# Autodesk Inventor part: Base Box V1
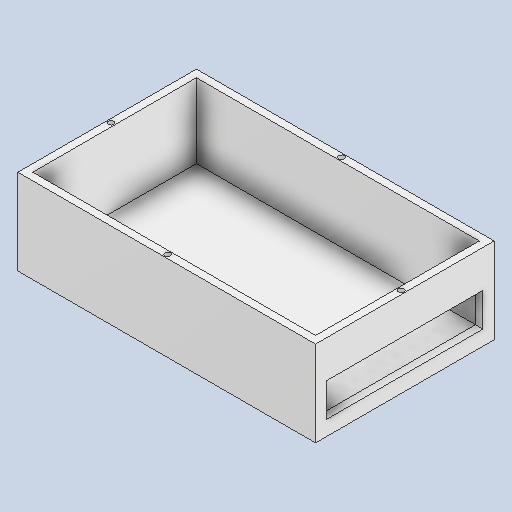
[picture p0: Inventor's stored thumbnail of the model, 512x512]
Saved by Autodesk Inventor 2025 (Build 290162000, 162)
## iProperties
Created: 2024-10
Part Number: Base Box V1
Material: ABS Plastic
Document SubType Name: Modeling
Designer: Braidyn
Density: 1.06 g/cm^3
Appearance: Smooth - White
Author: Braidyn
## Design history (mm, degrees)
sketch "Sketch1"
  geometry: L1 (-35.56, 30.48)-(35.56, 30.48); L2 (35.56, 30.48)-(35.56, -30.48); L3 (35.56, -30.48)-(-35.56, -30.48); L4 (-35.56, -30.48)-(-35.56, 30.48); L5 (-35.56, 30.48)-(35.56, -30.48); L6 (35.56, 30.48)-(-35.56, -30.48); L7 (-35.56, 30.48)-(-66.04, 30.48); L8 (-66.04, 30.48)-(-66.04, -30.48); L9 (-66.04, -30.48)-(-35.56, -30.48); L10 (-35.56, -30.48)-(-35.56, 30.48); 2 further points
  constraints: 20 end point, 4 parallel, 2 horizontal, 2 midpoint, 2 perpendicular
  dimensions: "d0" = 71.12 distance of L2.end L3.end; "d1" = 60.96 distance of L1.end L2.end; "d2" = 30.48 distance of L9.end L8.end
extrude "Extrusion1" new body sketch "Sketch1" distance "d3" = 3.81; taper "d4" = 0 deg
sketch "Sketch2"
  geometry: L1 (0, 0)-(-33.02, 0); L2 (0, 0)-(63.5, 0); L3 (66.04, -30.48)-(66.04, 30.48) reference; L4 (0, 0)-(0, 27.94); L5 (66.04, 30.48)-(-35.56, 30.48) reference; L6 (0, 27.94)-(0, -27.94); L7 (-33.02, -27.94)-(-33.02, 27.94); L8 (-33.02, 27.94)-(63.5, 27.94); L9 (63.5, 27.94)-(63.5, -27.94); L10 (63.5, -27.94)-(-33.02, -27.94); L11 (-35.56, -30.48)-(66.04, -30.48) reference; L12 (-35.56, -30.48)-(-35.56, 30.48); L13 (-35.56, 30.48)-(66.04, 30.48); L14 (66.04, 30.48)-(66.04, -30.48); L15 (66.04, -30.48)-(-35.56, -30.48)
  constraints: 24 end point, 4 perpendicular, 3 parallel, 2 collinear, 1 horizontal, 1 point on line, 1 vertical
  dimensions: "d5" = 33.02 distance of L1.start L1.end; "d6" = 63.5 distance of L1.start L2.end; "d7" = 27.94 distance of L1.start L4.end; "d8" = 55.88 distance of L4.end L6.end
extrude "Extrusion2" join sketch "Sketch2" distance "d9" = 25.4; taper "d10" = 0 deg
sketch "Sketch3"
  geometry: L1 (-33.02, 27.94)-(-33.02, -27.94) reference; L2 (63.5, 27.94)-(-33.02, 27.94) reference; L3 (-33.02, 27.94)-(63.5, 27.94); L4 (15.24, 27.94)-(15.24, 30.48); L5 (66.04, 30.48)-(-35.56, 30.48) reference; L6 (-33.02, -27.94)-(63.5, -27.94) reference; L7 (14.287, -27.94)-(14.287, -30.476); L8 (-35.56, 0)-(-33.02, 0); L9 (63.5, -27.94)-(63.5, 27.94) reference; L10 (63.5, 0)-(66.04, 0); L11 (66.04, -30.48)-(66.04, 30.48) reference; C1 r 0.952 at (15.24, 29.21); C2 r 0.952 at (14.287, -29.208); C3 r 0.953 at (-34.29, 0); C4 r 0.953 at (64.77, 0); 1 further point
  constraints: 10 end point, 9 midpoint, 4 centre point, 1 collinear, 1 perpendicular, 1 point on line
  dimensions: "d11" = 1.905 diameter of C1; "d12" = 1.905 diameter of C2; "d13" = 1.905 diameter of C3; "d14" = 1.905 diameter of C4
extrude "Extrusion3" cut sketch "Sketch3" distance "d15" = 3.81; taper "d16" = 0 deg
sketch "Sketch4"
  geometry: L1 (0, 0)-(0, 3.81); L2 (0, 0)-(0, 29.21) reference; L3 (0, 3.81)-(60.944, 3.81); L4 (0, 3.81)-(0, 5.08); L5 (0, 5.08)-(3.81, 5.08); L6 (60.944, 3.81)-(60.96, 5.08); L7 (60.96, 0)-(60.96, 29.21) reference; L8 (60.96, 5.08)-(57.15, 5.08); L9 (3.81, 5.08)-(57.15, 5.08); L10 (57.15, 5.08)-(57.15, 16.51); L11 (57.15, 16.51)-(3.81, 16.51); L12 (3.81, 16.51)-(3.81, 5.08); 1 further point
  constraints: 20 end point, 3 perpendicular, 3 point on line, 2 parallel, 1 collinear, 1 horizontal
  dimensions: "d17" = 3.81 distance of L1.start L1.end; "d18" = 1.27 distance of L1.end L4.end; "d19" = 3.81 distance of L4.end L5.end; "d20" = 3.81 distance of L6.end L8.end; "d21" = 11.43 distance of L10.end L8.end
extrude "Extrusion4" cut sketch "Sketch4" distance "d22" = 3.81; taper "d23" = 0 deg
body "Solid1"
